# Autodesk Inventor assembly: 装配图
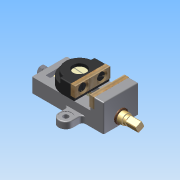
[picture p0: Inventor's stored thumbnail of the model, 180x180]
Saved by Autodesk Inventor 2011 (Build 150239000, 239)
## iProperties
Created: 2013-12
Part Number: 装配图
Document SubType Name: Assembly
Designer: Administrator
Author: Administrator
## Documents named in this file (11)
- C:\Documents and Settings\Administrator\桌面\机械制图\虎钳\装配图.iam
- C:\Documents and Settings\Administrator\桌面\机械制图\虎钳\钳座.ipt
- C:\Documents and Settings\Administrator\桌面\机械制图\虎钳\垫圈.ipt
- C:\Documents and Settings\Administrator\桌面\机械制图\虎钳\方块螺母.ipt
- C:\Documents and Settings\Administrator\桌面\机械制图\虎钳\护口板.ipt
- C:\Documents and Settings\Administrator\桌面\机械制图\虎钳\活动钳块.ipt
- C:\Documents and Settings\Administrator\桌面\机械制图\虎钳\螺钉 GB_T 68 M8 x 12.ipt
- C:\Documents and Settings\Administrator\桌面\机械制图\虎钳\螺钉.ipt
- C:\Documents and Settings\Administrator\桌面\机械制图\虎钳\螺杆.ipt
- C:\Documents and Settings\Administrator\桌面\机械制图\虎钳\螺母 GB_T 6170 M10.ipt
- C:\Documents and Settings\Administrator\桌面\机械制图\虎钳\平垫圈 GB_T 97.1 10.ipt
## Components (15 placed, 10 different names)
1. 钳座:1 — 插入:1, 插入:3, 配合:1, 表面齐平:1, 表面齐平:2, 配合:7, 表面齐平:4
2. 垫圈:1 — 插入:1, 插入:2
3. 护口板:1 — 配合:1, 表面齐平:1, 表面齐平:2, 配合:8, 配合:9, 相切:2, 配合:11, 相切:4
4. 活动钳块:1 — 配合:2, 配合:3, 表面齐平:3, 配合:7, 表面齐平:4, 配合:12
5. 螺钉 GB_T 68 M8 x 12:1 — 配合:4, 配合:5, 配合:6, 相切:1
6. 螺钉:1 — 插入:5
7. 螺杆:1 — 插入:2, 配合:13
8. 螺母 GB_T 6170 M10:1 — 插入:4, 插入:6
9. 平垫圈 GB_T 97.1 10:1 — 插入:3, 插入:4
10. 护口板:2 — 配合:2, 配合:3, 表面齐平:3, 配合:4, 配合:5, 配合:6, 相切:1, 配合:8, 配合:10, 相切:3
11. 螺钉 GB_T 68 M8 x 12:2 — 配合:11, 相切:4
12. 螺钉 GB_T 68 M8 x 12:3 — 配合:10, 相切:3
13. 螺钉 GB_T 68 M8 x 12:4 — 配合:9, 相切:2
14. 方块螺母:1 — 配合:12, 配合:13, 插入:5
15. 螺母 GB_T 6170 M10:2 — 插入:6
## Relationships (27: Mate 13, Insert 6, Flush 4, Tangent 4)
- 插入:1 [Insert]: 钳座:1 ↔ 垫圈:1
- 插入:2 [Insert]: 垫圈:1 ↔ 螺杆:1
- 插入:3 [Insert]: 钳座:1 ↔ 平垫圈 GB_T 97.1 10:1
- 插入:4 [Insert]: 螺母 GB_T 6170 M10:1 ↔ 平垫圈 GB_T 97.1 10:1
- 配合:1 [Mate]: 钳座:1 ↔ 护口板:1
- 表面齐平:1 [Flush]: 钳座:1 ↔ 护口板:1
- 表面齐平:2 [Flush]: 钳座:1 ↔ 护口板:1
- 配合:2 [Mate]: 活动钳块:1 ↔ 护口板:2
- 配合:3 [Mate]: 活动钳块:1 ↔ 护口板:2
- 表面齐平:3 [Flush]: 活动钳块:1 ↔ 护口板:2
- 配合:4 [Mate]: 螺钉 GB_T 68 M8 x 12:1 ↔ 护口板:2
- 配合:5 [Mate]: 螺钉 GB_T 68 M8 x 12:1 ↔ 护口板:2
- 配合:6 [Mate]: 螺钉 GB_T 68 M8 x 12:1 ↔ 护口板:2
- 相切:1 [Tangent]: 螺钉 GB_T 68 M8 x 12:1 ↔ 护口板:2
- 配合:7 [Mate]: 钳座:1 ↔ 活动钳块:1
- 表面齐平:4 [Flush]: 钳座:1 ↔ 活动钳块:1
- 配合:8 [Mate]: 护口板:1 ↔ 护口板:2
- 配合:9 [Mate]: 护口板:1 ↔ 螺钉 GB_T 68 M8 x 12:4
- 相切:2 [Tangent]: 护口板:1 ↔ 螺钉 GB_T 68 M8 x 12:4
- 配合:10 [Mate]: 护口板:2 ↔ 螺钉 GB_T 68 M8 x 12:3
- 相切:3 [Tangent]: 护口板:2 ↔ 螺钉 GB_T 68 M8 x 12:3
- 配合:11 [Mate]: 护口板:1 ↔ 螺钉 GB_T 68 M8 x 12:2
- 相切:4 [Tangent]: 护口板:1 ↔ 螺钉 GB_T 68 M8 x 12:2
- 配合:12 [Mate]: 活动钳块:1 ↔ 方块螺母:1
- 配合:13 [Mate]: 螺杆:1 ↔ 方块螺母:1
- 插入:5 [Insert]: 螺钉:1 ↔ 方块螺母:1
- 插入:6 [Insert]: 螺母 GB_T 6170 M10:1 ↔ 螺母 GB_T 6170 M10:2
